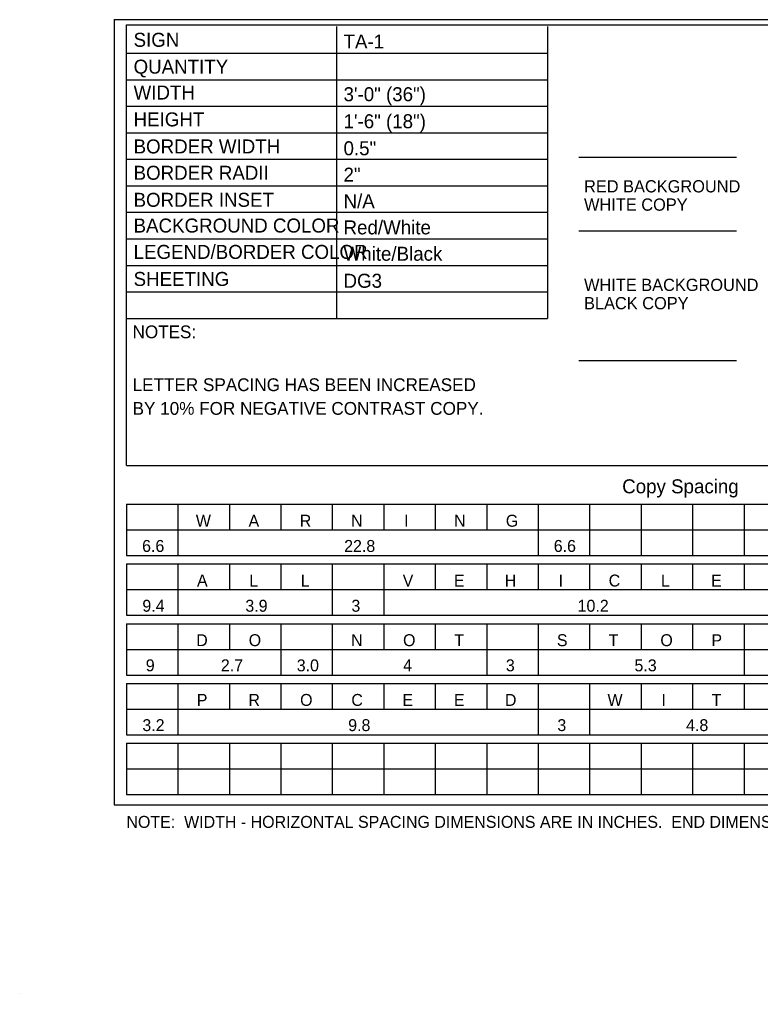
# Model space of a CAD drawing. Extents: x 53068 to 53703, y 9291 to 9710.
# Drawn here: x 53067.6 to 53241.3, y 9291.1 to 9519.5 of the extents above; entities that cross this region are included whole.
import ezdxf

# ---------------------------------------------------------------- set-up
doc = ezdxf.new("R2010")
doc.units = 0
for name, color, linetype in [('AdhocPoint_dp', 7, 'Continuous'), ('GSDims', 7, 'Continuous'), ('SheetLines_dp', 7, 'Continuous'), ('SumBoxLinesMin_dp', 7, 'Continuous'), ('TextMisc', 7, 'Continuous'), ('TextNotes', 7, 'Continuous')]:
    doc.layers.add(name, color=color, linetype=linetype)

msp = doc.modelspace()

# ---------------------------------------------------------------- linework, layer by layer
at = {"layer": 'AdhocPoint_dp'}
msp.add_line((53067.63, 9291.14), (53067.63, 9291.14), dxfattribs=at)
at = {"layer": 'GSDims'}
for p, q in [((53235.72, 9487.17), (53198.74, 9487.17)), ((53235.72, 9469.87), (53198.74, 9469.87)), ((53235.72, 9439.46), (53198.74, 9439.46))]:
    msp.add_line(p, q, dxfattribs=at)
at = {"layer": 'SheetLines_dp'}
for p, q in [((53089.8, 9519.5), (53089.8, 9335.4)), ((53089.8, 9519.5), (53391.35, 9519.5)), ((53089.8, 9335.4), (53391.35, 9335.4))]:
    msp.add_line(p, q, dxfattribs=at)
at = {"layer": 'SumBoxLinesMin_dp'}
for p, q in [((53092.7, 9518.25), (53389.3, 9518.25)), ((53092.7, 9414.91), (53092.7, 9518.25)), ((53141.91, 9517.83), (53141.91, 9449.41)), ((53191.41, 9517.83), (53191.41, 9449.41)), ((53092.7, 9511.61), (53191.41, 9511.61)), ((53092.7, 9505.39), (53191.41, 9505.39)), ((53092.7, 9499.17), (53191.41, 9499.17)), ((53092.7, 9492.95), (53191.41, 9492.95)), ((53092.7, 9486.73), (53191.41, 9486.73)), ((53092.7, 9480.51), (53191.41, 9480.51)), ((53092.7, 9474.29), (53191.41, 9474.29)), ((53092.7, 9468.07), (53191.41, 9468.07)), ((53092.7, 9461.85), (53191.41, 9461.85)), ((53092.7, 9455.63), (53191.41, 9455.63)), ((53092.7, 9449.41), (53191.41, 9449.41)), ((53092.7, 9414.91), (53389.3, 9414.91)), ((53092.7, 9405.87), (53389.3, 9405.87)), ((53092.7, 9405.87), (53092.7, 9393.83)), ((53104.76, 9405.87), (53104.76, 9393.83)), ((53116.83, 9405.87), (53116.83, 9399.85)), ((53128.89, 9405.87), (53128.89, 9399.85)), ((53140.96, 9405.87), (53140.96, 9399.85)), ((53153.02, 9405.87), (53153.02, 9399.85)), ((53165.09, 9405.87), (53165.09, 9399.85)), ((53177.16, 9405.87), (53177.16, 9399.85)), ((53189.22, 9405.87), (53189.22, 9393.83)), ((53201.29, 9405.87), (53201.29, 9393.83)), ((53213.35, 9405.87), (53213.35, 9393.83)), ((53225.42, 9405.87), (53225.42, 9393.83)), ((53237.48, 9405.87), (53237.48, 9393.83)), ((53092.7, 9399.85), (53346.08, 9399.85)), ((53092.7, 9393.83), (53389.3, 9393.83)), ((53092.7, 9391.86), (53389.3, 9391.86)), ((53092.7, 9391.86), (53092.7, 9379.81)), ((53104.76, 9391.86), (53104.76, 9379.81)), ((53116.83, 9391.86), (53116.83, 9385.83)), ((53128.89, 9391.86), (53128.89, 9385.83)), ((53140.96, 9391.86), (53140.96, 9379.81)), ((53153.02, 9391.86), (53153.02, 9379.81)), ((53165.09, 9391.86), (53165.09, 9385.83)), ((53177.16, 9391.86), (53177.16, 9385.83)), ((53189.22, 9391.86), (53189.22, 9385.83)), ((53201.29, 9391.86), (53201.29, 9385.83)), ((53213.35, 9391.86), (53213.35, 9385.83)), ((53225.42, 9391.86), (53225.42, 9385.83)), ((53237.48, 9391.86), (53237.48, 9385.83)), ((53092.7, 9385.83), (53346.08, 9385.83)), ((53092.7, 9379.81), (53389.3, 9379.81)), ((53092.7, 9377.85), (53389.3, 9377.85)), ((53092.7, 9377.85), (53092.7, 9365.79)), ((53104.76, 9377.85), (53104.76, 9365.79)), ((53116.83, 9377.85), (53116.83, 9371.82)), ((53128.89, 9377.85), (53128.89, 9365.79)), ((53140.96, 9377.85), (53140.96, 9365.79)), ((53153.02, 9377.85), (53153.02, 9371.82)), ((53165.09, 9377.85), (53165.09, 9371.82)), ((53177.16, 9377.85), (53177.16, 9365.79)), ((53189.22, 9377.85), (53189.22, 9365.79)), ((53201.29, 9377.85), (53201.29, 9371.82)), ((53213.35, 9377.85), (53213.35, 9371.82)), ((53225.42, 9377.85), (53225.42, 9371.82)), ((53237.48, 9377.85), (53237.48, 9365.79)), ((53092.7, 9371.82), (53346.08, 9371.82)), ((53092.7, 9365.79), (53389.3, 9365.79)), ((53092.7, 9363.83), (53389.3, 9363.83)), ((53092.7, 9363.83), (53092.7, 9351.78)), ((53104.76, 9363.83), (53104.76, 9351.78)), ((53116.83, 9363.83), (53116.83, 9357.81)), ((53128.89, 9363.83), (53128.89, 9357.81)), ((53140.96, 9363.83), (53140.96, 9357.81)), ((53153.02, 9363.83), (53153.02, 9357.81)), ((53165.09, 9363.83), (53165.09, 9357.81)), ((53177.16, 9363.83), (53177.16, 9357.81)), ((53189.22, 9363.83), (53189.22, 9351.78)), ((53201.29, 9363.83), (53201.29, 9351.78)), ((53213.35, 9363.83), (53213.35, 9357.81)), ((53225.42, 9363.83), (53225.42, 9357.81)), ((53237.48, 9363.83), (53237.48, 9357.81)), ((53092.7, 9357.81), (53358.14, 9357.81)), ((53092.7, 9351.78), (53389.3, 9351.78)), ((53092.7, 9349.82), (53389.3, 9349.82)), ((53092.7, 9349.82), (53092.7, 9337.77)), ((53104.76, 9349.82), (53104.76, 9337.77)), ((53116.83, 9349.82), (53116.83, 9337.77)), ((53128.89, 9349.82), (53128.89, 9337.77)), ((53140.96, 9349.82), (53140.96, 9337.77)), ((53153.02, 9349.82), (53153.02, 9337.77)), ((53165.09, 9349.82), (53165.09, 9337.77)), ((53177.16, 9349.82), (53177.16, 9337.77)), ((53189.22, 9349.82), (53189.22, 9337.77)), ((53201.29, 9349.82), (53201.29, 9337.77)), ((53213.35, 9349.82), (53213.35, 9337.77)), ((53225.42, 9349.82), (53225.42, 9337.77)), ((53237.48, 9349.82), (53237.48, 9337.77)), ((53092.7, 9343.79), (53346.08, 9343.79)), ((53092.7, 9337.77), (53389.3, 9337.77))]:
    msp.add_line(p, q, dxfattribs=at)

# ---------------------------------------------------------------- texts
at = {"layer": 'GSDims'}
for s, height, p in [('SIGN', 3.281, (53094.38, 9513.1)), ('TA-1', 3.281, (53143.6, 9512.7)), ('QUANTITY', 3.281, (53094.38, 9506.8)), ('WIDTH', 3.281, (53094.38, 9500.74)), ('3\'-0" (36")', 3.2807, (53143.6, 9500.34)), ('HEIGHT', 3.281, (53094.38, 9494.44)), ('1\'-6" (18")', 3.2807, (53143.6, 9494)), ('BORDER WIDTH', 3.2807, (53094.38, 9488.1)), ('0.5"', 3.281, (53143.6, 9487.67)), ('BORDER RADII', 3.2807, (53094.38, 9481.92)), ('2"', 3.281, (53143.6, 9481.48)), ('RED BACKGROUND', 2.8669, (53199.98, 9478.96)), ('BORDER INSET', 3.2807, (53094.38, 9475.58)), ('N/A', 3.281, (53143.6, 9475.26)), ('WHITE COPY', 2.867, (53199.98, 9474.67)), ('BACKGROUND COLOR', 3.2807, (53094.38, 9469.55)), ('Red/White', 3.281, (53143.6, 9469.12)), ('LEGEND/BORDER COLOR', 3.2807, (53094.38, 9463.37)), ('White/Black', 3.2807, (53143.6, 9462.94)), ('SHEETING', 3.281, (53094.38, 9457.03)), ('DG3', 3.281, (53143.6, 9456.6)), ('WHITE BACKGROUND', 2.8669, (53199.98, 9455.85)), ('BLACK COPY', 2.867, (53199.98, 9451.56)), ('Copy Spacing', 3.2807, (53208.92, 9408.41)), ('W', 2.8, (53108.98, 9400.58)), ('A', 2.8, (53121.33, 9400.58)), ('R', 2.8, (53133.33, 9400.58)), ('N', 2.8, (53145.37, 9400.58)), ('I', 2.8, (53157.8, 9400.58)), ('N', 2.8, (53169.51, 9400.58)), ('G', 2.8, (53181.64, 9400.58)), ('6.6', 2.8, (53096.38, 9394.67)), ('22.8', 2.8, (53143.74, 9394.67)), ('6.6', 2.8, (53192.88, 9394.67)), ('A', 2.8, (53109.24, 9386.56)), ('L', 2.8, (53121.49, 9386.56)), ('L', 2.8, (53133.58, 9386.56)), ('V', 2.8, (53157.47, 9386.56)), ('E', 2.8, (53169.46, 9386.56)), ('H', 2.8, (53181.39, 9386.56)), ('I', 2.8, (53194.02, 9386.56)), ('C', 2.8, (53205.75, 9386.56)), ('L', 2.8, (53217.99, 9386.56)), ('E', 2.8, (53229.78, 9386.56)), ('9.4', 2.8, (53096.44, 9380.65)), ('3.9', 2.8, (53120.58, 9380.65)), ('3', 2.8, (53145.45, 9380.65)), ('10.2', 2.8, (53198.47, 9380.65)), ('D', 2.8, (53109.06, 9372.58)), ('O', 2.8, (53121.37, 9372.58)), ('N', 2.8, (53145.37, 9372.58)), ('O', 2.8, (53157.55, 9372.58)), ('T', 2.8, (53169.57, 9372.58)), ('S', 2.8, (53193.61, 9372.58)), ('T', 2.8, (53205.75, 9372.58)), ('O', 2.8, (53217.87, 9372.58)), ('P', 2.8, (53229.83, 9372.58)), ('9', 2.8, (53097.24, 9366.68)), ('2.7', 2.8, (53114.84, 9366.68)), ('3.0', 2.8, (53132.63, 9366.68)), ('4', 2.8, (53157.57, 9366.68)), ('3', 2.8, (53181.65, 9366.68)), ('5.3', 2.8, (53211.8, 9366.68)), ('P', 2.8, (53109.2, 9358.57)), ('R', 2.8, (53121.29, 9358.57)), ('O', 2.8, (53133.42, 9358.57)), ('C', 2.8, (53145.43, 9358.57)), ('E', 2.8, (53157.42, 9358.57)), ('E', 2.8, (53169.46, 9358.57)), ('D', 2.8, (53181.43, 9358.57)), ('W', 2.8, (53205.48, 9358.57)), ('I', 2.8, (53218.11, 9358.57)), ('T', 2.8, (53229.88, 9358.57)), ('3.2', 2.8, (53096.44, 9352.66)), ('9.8', 2.8, (53144.69, 9352.66)), ('3', 2.8, (53193.72, 9352.66)), ('4.8', 2.8, (53223.9, 9352.66))]:
    msp.add_text(s, height=height, dxfattribs=at).set_placement(p)
at = {"layer": 'TextMisc'}
for s, height, p in [('NOTES:', 2.99, (53094.15, 9444.77)), ('LETTER SPACING HAS BEEN INCREASED', 3, (53094.15, 9432.37)), ('BY 10% FOR NEGATIVE CONTRAST COPY.', 3, (53094.15, 9426.82))]:
    msp.add_text(s, height=height, dxfattribs=at).set_placement(p)
at = {"layer": 'TextNotes'}
msp.add_text('NOTE:  WIDTH - HORIZONTAL SPACING DIMENSIONS ARE IN INCHES.  END DIMENSIONS INCLUDE BORDER WIDTH, MARGIN, AND BORDER RECESS.', height=2.8, dxfattribs=at).set_placement((53092.7, 9329.98))

doc.saveas('drawing.dxf')
